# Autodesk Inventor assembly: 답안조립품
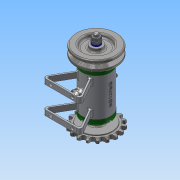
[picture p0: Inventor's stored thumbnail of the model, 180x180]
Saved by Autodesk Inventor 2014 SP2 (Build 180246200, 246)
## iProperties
Created: 2016-03
Part Number: 답안조립품
Document SubType Name: Assembly
Designer: 703
Author: 703
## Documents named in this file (15)
- C:\Users\703\Desktop\460307V1004\답안조립품.iam
- C:\Users\703\Desktop\460307V1004\본체.ipt
- C:\Users\703\Desktop\460307V1004\축.ipt
- C:\Users\703\Desktop\460307V1004\키 3 x 3 x 12.ipt
- C:\Users\703\Desktop\460307V1004\베어링 15 x 32 x 9.ipt
- C:\Users\703\Desktop\460307V1004\커버.ipt
- C:\Users\703\Desktop\460307V1004\V벨트풀리.ipt
- C:\Users\703\Desktop\460307V1004\스프로킷.ipt
- C:\Users\703\Desktop\460307V1004\스프링와셔 8.ipt
- C:\Users\703\Desktop\460307V1004\와셔 6x11.5.ipt
- C:\Users\703\Desktop\460307V1004\너트 M 8.ipt
- C:\Users\703\Desktop\460307V1004\볼트 M4 x 12.ipt
- C:\Users\703\Desktop\460307V1004\볼트 M 6 x 8.ipt
- C:\Users\703\Desktop\460307V1004\오일 실 15 25 7.ipt
- C:\Users\703\Desktop\460307V1004\니플 M 6 x 0.75.ipt
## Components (11 placed, 3 different names)
1. KS B 2023 6002 - 15 x 32 x 9:1
2. KS B 2023 6002 - 15 x 32 x 9:2
3. V벨트풀리:1 — 각도:3
4. ISO 4762 M4 x 12:1
5. ISO 4762 M4 x 12:2
6. ISO 4762 M4 x 12:3
7. ISO 4762 M4 x 12:4
8. ISO 4762 M4 x 12:5
9. ISO 4762 M4 x 12:6
10. ISO 4762 M4 x 12:7
11. ISO 4762 M4 x 12:8
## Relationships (1: Angle 1)
- 각도:3 [Angle]: V벨트풀리:1
